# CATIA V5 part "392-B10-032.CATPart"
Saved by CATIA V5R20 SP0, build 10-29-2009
Part number: 392-B10-032
Definition: NONE
Nomenclature: 392-B10-032
Source: Unknown
Description: 392-B10-032
Bounding box of the stored display mesh (mm): x 0 to 32, y -4.695 to 4.695, z -4.65 to 4.65
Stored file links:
  C:\Users\Utente\Desktop\IO LAVORO\3D X SITO CF\X SITO\3D files 392B\392-B10-032.CATPart
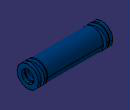
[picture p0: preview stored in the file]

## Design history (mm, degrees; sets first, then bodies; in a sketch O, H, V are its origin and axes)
Body1 "392-B10-032" (main body)
  Solid1: solid without history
